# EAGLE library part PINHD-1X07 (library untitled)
PIN HEADER
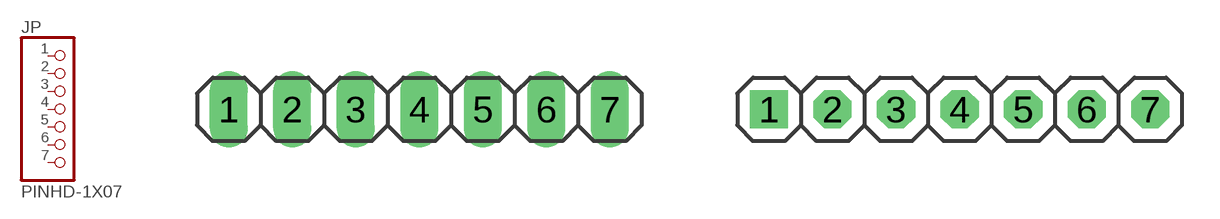
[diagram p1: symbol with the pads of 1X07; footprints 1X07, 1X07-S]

Designator prefix JP

## PINHD-1X07_2.54  [1X07]
1  1  pas
2  2  pas
3  3  pas
4  4  pas
5  5  pas
6  6  pas
7  7  pas

## PINHD-1X07_2.54-S  [1X07-S]
Pads as for 1X07

## PINHD-1X07_2.54-90°  [1X07/90]
Pads as for 1X07

## PINHD-1X07_2.54-90°-S  [1X07/90-S]
Pads as for 1X07

## PINHD-1X07_2.00  [1X07M]
Pads as for 1X07

## PINHD-1X07_2.54-SMD  [1X07SMD]
Pads as for 1X07

## PINHD-1X07_2.54-SMD-90°  [1X07SMD/90]
Pads as for 1X07

## Footprint 1X07 (pad centres in mm)
PIN HEADER - 2.54
drill 1.016 long: 1 -7.62,0; 2 -5.08,0; 3 -2.54,0; 4 0,0; 5 2.54,0; 6 5.08,0; 7 7.62,0

## Footprint 1X07-S (pad centres in mm)
PIN HEADER - 2.54
drill 1.016 square: 1 -7.62,0
drill 1.016 octagon: 2 -5.08,0; 3 -2.54,0; 4 0,0; 5 2.54,0; 6 5.08,0; 7 7.62,0

## Footprint 1X07/90 (pad centres in mm)
PIN HEADER - 2.54 90°
drill 1.016 long: 1 -7.62,-3.81; 2 -5.08,-3.81; 3 -2.54,-3.81; 4 0,-3.81; 5 2.54,-3.81; 6 5.08,-3.81; 7 7.62,-3.81

## Footprint 1X07/90-S (pad centres in mm)
PIN HEADER - 2.54 90°
drill 1.016 square: 1 -7.62,-3.81
drill 1.016 octagon: 2 -5.08,-3.81; 3 -2.54,-3.81; 4 0,-3.81; 5 2.54,-3.81; 6 5.08,-3.81; 7 7.62,-3.81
